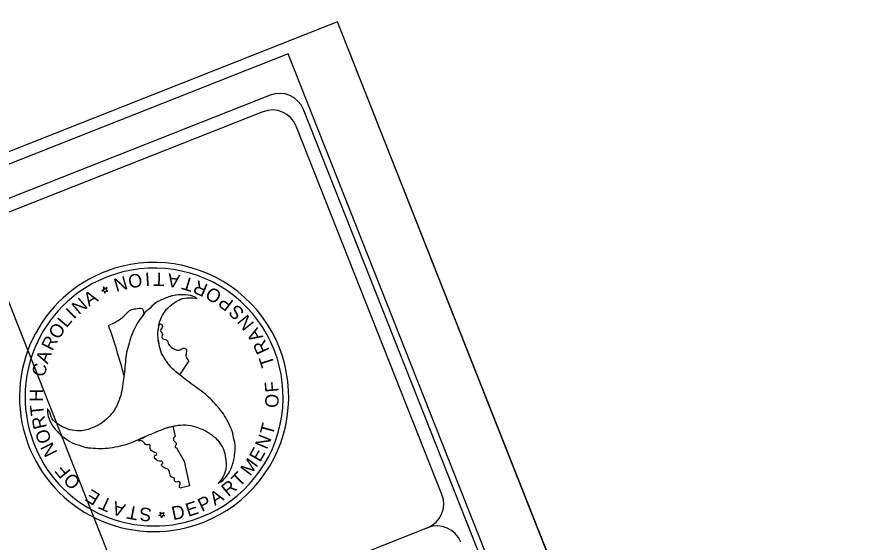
# Model space of a CAD drawing. Extents: x 1247235 to 1260080, y 742320 to 754020.
# Drawn here: x 1251273 to 1252768, y 750916 to 751842 of the extents above; entities that cross this region are included whole.
import ezdxf

# ---------------------------------------------------------------- set-up
doc = ezdxf.new("R2010")
doc.units = 0
for name, color, linetype in [('Scratch_Level_1', 7, 'Continuous'), ('Sheet Cutting Line CELL', 7, 'Continuous'), ('Sheet Plot Border Inside CELL', 7, 'Continuous'), ('Sheet Plot Border Outside CELL', 7, 'Continuous'), ('Sheet Title CELL', 7, 'Continuous')]:
    doc.layers.add(name, color=color, linetype=linetype)

msp = doc.modelspace()

# ---------------------------------------------------------------- linework, layer by layer
at = {"layer": 'Scratch_Level_1'}
msp.add_line((1251585.7, 750513), (1251023.8, 751934), dxfattribs=at)
at = {"layer": 'Sheet Cutting Line CELL'}
msp.add_line((1254624.4, 744786.1), (1251837.9, 751833.2), dxfattribs=at)
at = {"layer": 'Sheet Plot Border Inside CELL'}
msp.add_lwpolyline([(1254509, 744803.4), (1251751.5, 751777.2), (1247336.2, 750031.4), (1250093.7, 743057.5)], close=True, dxfattribs=at)
at = {"layer": 'Sheet Plot Border Outside CELL'}
msp.add_lwpolyline([(1247234.8, 750013.1), (1250021.3, 742966), (1254624.4, 744786.1), (1251837.9, 751833.2)], close=True, dxfattribs=at)
at = {"layer": 'Sheet Title CELL'}
for p, q in [((1251457.7, 751402.1), (1251457.7, 751402.1)), ((1251426.5, 751361.6), (1251423.2, 751359.3)), ((1251423.2, 751359.3), (1251427.2, 751359)), ((1251428.7, 751362.8), (1251425.4, 751365.4)), ((1251425.4, 751365.4), (1251426.5, 751361.6)), ((1251427.2, 751359), (1251428.2, 751355)), ((1251428.2, 751355), (1251429.7, 751358.9)), ((1251432.2, 751365), (1251428.7, 751362.8)), ((1251429.7, 751358.9), (1251433.8, 751358.7)), ((1251430.7, 751361.2), (1251432.2, 751365)), ((1251433.8, 751358.7), (1251430.7, 751361.2)), ((1251576.1, 751235.8), (1251560, 751211.2)), ((1251461.9, 751210.8), (1251461.9, 751210.8)), ((1251560, 751211.2), (1251560, 751211.2)), ((1251326.7, 751150.9), (1251327.3, 751150.6)), ((1251326.7, 751150.9), (1251327.3, 751150.6)), ((1251548.1, 751120.7), (1251552.4, 751102.4)), ((1251554.4, 751082.4), (1251568, 751059.2)), ((1251568, 751059.2), (1251577.2, 751015.2)), ((1251577.2, 751015.2), (1251563.2, 751012.2)), ((1251523.3, 750963), (1251526.7, 750965.2)), ((1251526.7, 750965.2), (1251525.7, 750969.2)), ((1251525.7, 750969.2), (1251528.9, 750966.5)), ((1251528.9, 750966.5), (1251532.4, 750968.7)), ((1251532.4, 750968.7), (1251530.8, 750964.8)), ((1251530.8, 750964.8), (1251534, 750962.4)), ((1251527.3, 750962.8), (1251523.3, 750963)), ((1251528.3, 750958.8), (1251527.3, 750962.8)), ((1251529.9, 750962.6), (1251528.3, 750958.8)), ((1251534, 750962.4), (1251529.9, 750962.6)), ((1251996.9, 750941.6), (1251327.3, 750676.9))]:
    msp.add_line(p, q, dxfattribs=at)
for points in [[(1251719.6, 751704.2), (1247409.4, 749999.8)], [(1251706.9, 751674.9), (1251037.4, 751410.2)], [(1254227, 745485.4), (1251778, 751678.9)], [(1252022.2, 751000), (1251765.3, 751649.6)]]:
    msp.add_lwpolyline(points, dxfattribs=at)
for centre, radius, start, end in [((1251736.2, 751662.3), 45, 21.5743, 111.5743), ((1251723.5, 751633.1), 45, 21.5743, 111.5743), ((1251515.1, 751172), 237.2, 103.9955, 283.9955), ((1251515.1, 751172), 237.2, 283.9955, 103.9955), ((1251515.1, 751172), 227.3, 283.9955, 103.9955), ((1251515.1, 751172), 227.3, 103.9955, 283.9955), ((1250254.4, 750884.7), 1250.8, 15.113, 19.319), ((1250254.4, 750884.7), 1250.8, 9.674, 9.7736), ((1251980.3, 750983.5), 45, 291.5743, 21.5743), ((1252013.4, 750899.8), 45, 21.5743, 111.5743)]:
    msp.add_arc(centre, radius, start, end, dxfattribs=at)
for points in [[(1251590.9, 751345.7), (1251586.3, 751348.4), (1251571, 751352.2), (1251554.1, 751351.7), (1251552.5, 751351.5), (1251543.7, 751349.5), (1251533.7, 751345.7), (1251517.9, 751337.8), (1251504.5, 751325.9), (1251498.8, 751321), (1251493.8, 751314.1), (1251484.2, 751299.5), (1251477, 751284.8), (1251470.9, 751266.9), (1251466.7, 751250.8), (1251464.5, 751233.7), (1251462.7, 751216.5), (1251460.5, 751200), (1251458, 751182.7), (1251453.4, 751166.5), (1251452.8, 751165.2), (1251444.9, 751148.4), (1251433.5, 751135.3), (1251420.9, 751125), (1251413.9, 751121), (1251404.5, 751117.2), (1251399.1, 751114.8), (1251387.3, 751112.7), (1251370.5, 751113.4), (1251355.7, 751118.6), (1251343.2, 751126), (1251333.5, 751137.2), (1251327.3, 751150.6), (1251326.7, 751150.9)], [(1251628, 751019.7), (1251632.8, 751022.6), (1251643.7, 751034), (1251651.8, 751048.7), (1251652.2, 751050.2), (1251655.1, 751059), (1251656.7, 751069.4), (1251657.7, 751087.2), (1251654.2, 751104.6), (1251652.7, 751111.9), (1251649.1, 751120), (1251641.4, 751135.3), (1251632.3, 751148.8), (1251619.8, 751163.2), (1251608.1, 751174.8), (1251594.3, 751185.3), (1251580.3, 751195.4), (1251567, 751205.7), (1251553.5, 751216.5), (1251541.6, 751228.5), (1251540.6, 751230), (1251530.2, 751245), (1251524.6, 751261.3), (1251522, 751277.2), (1251521.7, 751285.7), (1251523.4, 751295.5), (1251523.9, 751301.5), (1251528, 751312.7), (1251537, 751326.7), (1251548.9, 751337), (1251561.7, 751344.3), (1251576.1, 751347.1), (1251590.9, 751345.7)], [(1251434.8, 751298.4), (1251449.3, 751305.5), (1251465.4, 751318.1), (1251474, 751325.7), (1251482.6, 751327.7), (1251493.2, 751328.3), (1251496.7, 751318.7)], [(1251496.8, 751318.7), (1251493.8, 751314.1), (1251484.2, 751299.5), (1251477, 751284.8), (1251470.9, 751266.9), (1251466.7, 751250.8), (1251464.5, 751233.7), (1251462.7, 751216.5), (1251461.9, 751210.8)], [(1251560, 751211.2), (1251553.5, 751216.5), (1251541.6, 751228.5), (1251540.6, 751230), (1251530.2, 751245), (1251524.6, 751261.3), (1251522, 751277.2), (1251521.7, 751285.7), (1251523.4, 751295.5), (1251523.9, 751301.1)], [(1251524, 751301), (1251528.6, 751299.9), (1251529.7, 751296.5), (1251526.4, 751289.2), (1251529.7, 751282.2), (1251528.6, 751278.3), (1251529.1, 751276), (1251537.2, 751272.3), (1251540.7, 751265.3), (1251552.4, 751255.6), (1251558.2, 751254.4), (1251569, 751258), (1251571.9, 751255.6), (1251572.2, 751252), (1251571.2, 751243.9), (1251576.1, 751235.8)], [(1251327.3, 751150.6), (1251327.2, 751145.1), (1251331.6, 751130), (1251340.5, 751115.6), (1251341.6, 751114.5), (1251347.6, 751107.7), (1251355.8, 751101), (1251370.7, 751091.4), (1251387.6, 751085.5), (1251394.8, 751083.2), (1251403.1, 751082.3), (1251420.7, 751081.3), (1251437, 751082.5), (1251455.6, 751086.1), (1251471.7, 751090.4), (1251487.4, 751097.1), (1251503.3, 751104.1), (1251518.8, 751110.5), (1251534.8, 751116.9), (1251551.2, 751121.1), (1251552.7, 751121.4), (1251571, 751122.8), (1251588.1, 751119.5), (1251603.3, 751113.6), (1251610.5, 751109.7), (1251618.5, 751103.5), (1251623, 751100), (1251630.9, 751090.9), (1251638.6, 751076), (1251641.5, 751060.4), (1251641.4, 751045.9), (1251636.7, 751031.9), (1251628, 751019.7)], [(1251487, 751097), (1251487.4, 751097.1), (1251503.3, 751104.1), (1251518.8, 751110.5), (1251534.8, 751116.9), (1251548.1, 751120.6)], [(1251552.4, 751102.4), (1251549.5, 751099.8), (1251549.4, 751096), (1251553.1, 751091.8), (1251553.8, 751088.2), (1251551.9, 751083.5), (1251554.4, 751082.4)], [(1251563.2, 751012.2), (1251562.1, 751011.4), (1251560, 751013.3), (1251561, 751020.5), (1251557.4, 751023), (1251554.7, 751022.2), (1251551.2, 751024.1), (1251551, 751028.8), (1251544.9, 751031.5), (1251543.1, 751035), (1251541.1, 751042.8), (1251529.6, 751049.7), (1251528, 751053.4), (1251530.3, 751055), (1251530.1, 751057.5), (1251521.5, 751059.5), (1251520.2, 751060.3), (1251515.5, 751066.8), (1251516.4, 751069.1), (1251519.7, 751070.4), (1251520.1, 751071.6), (1251517.8, 751073.6), (1251512.9, 751075.8), (1251508.3, 751081), (1251507.5, 751087.9), (1251501.7, 751087.7), (1251494.4, 751094.3), (1251490.8, 751095.1), (1251487.4, 751094.7)]]:
    msp.add_spline(points, degree=3, dxfattribs=at)

# ---------------------------------------------------------------- texts
for s, height, rotation, p in [('N', 23.7, 196.2036, (1251463.8, 751385.9)), ('O', 23.6, 188.9556, (1251492, 751390.6)), ('I', 23.7, 183.82, (1251507.1, 751391.7)), ('T', 23.6, 178.1701, (1251533.8, 751391)), ('A', 23.7, 171.0856, (1251561.6, 751387)), ('T', 23.6, 162.9986, (1251587.3, 751379.6)), ('R', 23.7, 156.8988, (1251611.6, 751369.6)), ('A', 23.7, 32.4588, (1251400.3, 751331)), ('O', 23.7, 149.7097, (1251636.3, 751355.3)), ('N', 23.6, 39.8908, (1251382.4, 751316.2)), ('P', 23.6, 143.0177, (1251656.7, 751340.3)), ('I', 23.7, 45.5909, (1251374.2, 751308.1)), ('S', 23.6, 135.8259, (1251675.6, 751322.1)), ('L', 23.6, 49.5803, (1251360.6, 751292.8)), ('N', 23.6, 128.6154, (1251692.6, 751301.5)), ('O', 23.7, 55.8139, (1251346.5, 751272)), ('A', 23.6, 121.5838, (1251707.7, 751278)), ('R', 23.6, 62.9335, (1251336.1, 751251.9)), ('R', 23.7, 114.8306, (1251719, 751254.4)), ('A', 23.6, 69.2975, (1251327.6, 751229.2)), ('T', 23.6, 107.874, (1251727.5, 751229)), ('C', 23.6, 76.7945, (1251322.1, 751206.2)), ('F', 23.6, 94.9648, (1251734.7, 751181.2)), ('H', 23.6, 89.1369, (1251319.2, 751163.5)), ('O', 23.6, 87.7995, (1251734, 751152.6)), ('T', 23.7, 96.2216, (1251321.6, 751140.4)), ('R', 23.7, 102.8712, (1251326.6, 751118.4)), ('O', 23.7, 109.4811, (1251335, 751094.8)), ('T', 23.6, 74.4959, (1251723.8, 751103.1)), ('N', 23.7, 67.6539, (1251713.9, 751078.4)), ('N', 23.7, 116.9793, (1251345.3, 751074.1)), ('E', 23.6, 60.6823, (1251701.7, 751056)), ('M', 23.6, 53.2155, (1251684.1, 751031.6)), ('F', 23.7, 129.0662, (1251369.5, 751040.8)), ('T', 23.6, 45.9805, (1251665.7, 751012)), ('O', 23.7, 136.213, (1251387.5, 751023.4)), ('R', 23.6, 39.33, (1251645.6, 750995.3)), ('E', 23.6, 148.1524, (1251422, 750999.5)), ('T', 23.6, 155.268, (1251443, 750989.7)), ('P', 23.7, 25.6688, (1251599.3, 750969.1)), ('A', 23.6, 32.2613, (1251622.1, 750980)), ('A', 23.7, 162.3233, (1251466.3, 750982.3)), ('T', 23.7, 169.3756, (1251488.9, 750977.7)), ('D', 23.7, 11.8485, (1251548.6, 750954.8)), ('E', 23.6, 18.1364, (1251575.1, 750960.6)), ('S', 23.6, 175.7517, (1251511.4, 750976))]:
    msp.add_text(s, height=height, rotation=rotation, dxfattribs=at).set_placement(p)

doc.saveas('drawing.dxf')
